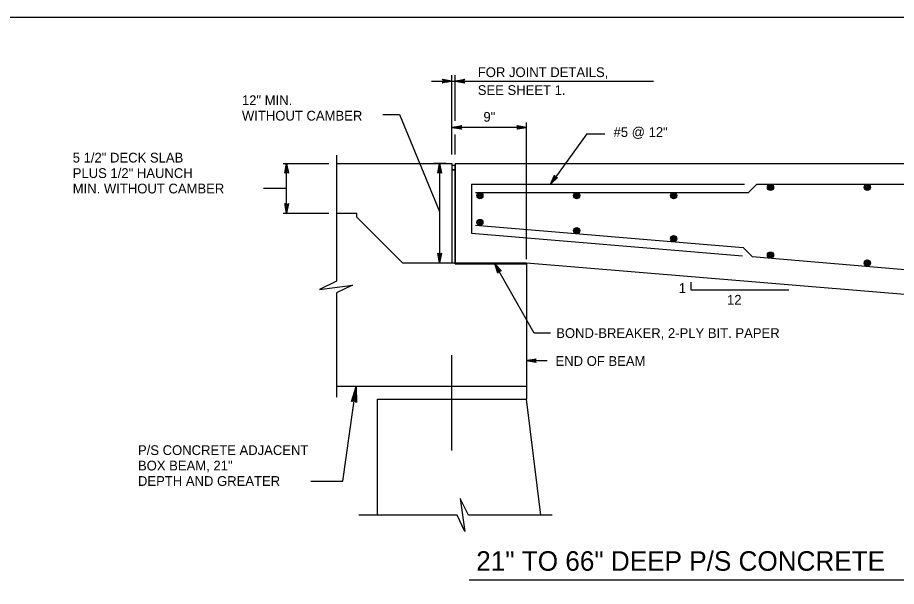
# Model space of a CAD drawing. Extents: x 638079 to 640019, y 297691 to 298879.
# Drawn here: x 638704.2 to 638974.3, y 298095.3 to 298270.2 of the extents above; entities that cross this region are included whole.
import ezdxf

# ---------------------------------------------------------------- set-up
doc = ezdxf.new("R2010")
doc.units = 0
doc.layers.add('1', color=7, linetype='Continuous')

msp = doc.modelspace()

# ---------------------------------------------------------------- linework, layer by layer
at = {"layer": '1'}
for p, q in [((638831.35, 298250.68), (638899.57, 298250.68)), ((638837.68, 298228.12), (638837.68, 298252.54)), ((638838.63, 298238.5), (638838.63, 298252.54)), ((638860.54, 298195.99), (638860.54, 298237.97)), ((638860.54, 298236.45), (638837.68, 298236.45)), ((638838.63, 298228.12), (638838.63, 298234.3)), ((638879.1, 298234.45), (638867.94, 298218.98)), ((638879.1, 298234.45), (638884.65, 298234.45)), ((638802.14, 298227.96), (638802.14, 298189.16)), ((638785.76, 298225.33), (638799.81, 298225.33)), ((638786.87, 298210.09), (638786.87, 298225.33)), ((638802.14, 298225.33), (638837.68, 298225.33)), ((638835.93, 298225.33), (638832.14, 298225.33)), ((638833.89, 298225.33), (638833.89, 298194.85)), ((638837.68, 298225.33), (638837.68, 298194.85)), ((638837.68, 298223.42), (638838.63, 298223.42)), ((638838.63, 298225.33), (639069.29, 298225.33)), ((638838.63, 298225.33), (638838.63, 298194.85)), ((638779.73, 298217.81), (638786.87, 298217.81)), ((638843.71, 298218.98), (638843.71, 298203.9)), ((638843.71, 298218.98), (638927.53, 298218.98)), ((638928.81, 298216.44), (638931.34, 298218.98)), ((638931.34, 298218.98), (639069.48, 298218.98)), ((638844.93, 298216.44), (638928.81, 298216.44)), ((638785.76, 298210.09), (638799.81, 298210.09)), ((638802.14, 298210.09), (638808.47, 298210.09)), ((638808.47, 298208.82), (638808.47, 298210.09)), ((638822.44, 298194.85), (638808.47, 298208.82)), ((638844.93, 298206.35), (638927.17, 298199.49)), ((638843.71, 298203.9), (638926.96, 298196.96)), ((638927.17, 298199.49), (638929.95, 298196.72)), ((638929.95, 298196.72), (638982.77, 298192.31)), ((638822.44, 298194.85), (638860.54, 298194.85)), ((638838.63, 298194.85), (638860.54, 298194.85)), ((638838.63, 298194.55), (638838.63, 298194.85)), ((638838.63, 298194.55), (638838.63, 298194.85)), ((638838.63, 298194.55), (638860.54, 298194.55)), ((638860.54, 298194.85), (638860.54, 298152.94)), ((638860.54, 298194.85), (638982.45, 298184.69)), ((638802.14, 298185.64), (638802.14, 298153.56)), ((638837.68, 298137.11), (638837.68, 298166.41)), ((638860.54, 298164.75), (638866.94, 298164.75)), ((638860.54, 298156.75), (638802.14, 298156.75)), ((638804.11, 298127.72), (638808.26, 298156.75)), ((638814.82, 298152.94), (638860.54, 298152.94)), ((638814.82, 298117.2), (638814.82, 298152.94)), ((638865.01, 298117.2), (638860.54, 298152.94)), ((638794.31, 298127.72), (638804.11, 298127.72)), ((638839.26, 298117.2), (638809.08, 298117.2)), ((638868.45, 298117.2), (638842.77, 298117.2)), ((638842.97, 298097.37), (639012.44, 298097.37))]:
    msp.add_line(p, q, dxfattribs=at)
for points in [[(639099.03, 297706.23), (639099.03, 298270.23), (638313.03, 298270.23), (638313.03, 297706.23), (639099.03, 297706.23), (639099.03, 297732.59), (638899.03, 297732.59), (638899.03, 297797.26), (639099.03, 297797.26), (639099.03, 297826.23), (638899.03, 297826.23), (638899.03, 297706.23), (638977.83, 297706.23), (638977.83, 297732.59), (638977.83, 297706.23), (639054.83, 297706.23), (639054.83, 297732.59), (639054.83, 297720.27), (639099.03, 297720.27)], [(638837.68, 298250.68), (638834.7, 298250.12), (638834.81, 298250.2), (638834.93, 298250.28), (638834.99, 298250.38), (638835.05, 298250.48), (638835.06, 298250.58), (638835.08, 298250.68), (638835.06, 298250.78), (638835.05, 298250.88), (638834.99, 298250.98), (638834.93, 298251.08), (638834.81, 298251.16), (638834.7, 298251.24), (638837.68, 298250.68), (638834.81, 298251.16), (638834.93, 298251.08), (638837.68, 298250.68), (638834.99, 298250.98), (638835.05, 298250.88), (638837.68, 298250.68), (638835.06, 298250.78), (638835.08, 298250.68), (638837.68, 298250.68), (638835.06, 298250.58), (638835.05, 298250.48), (638837.68, 298250.68), (638834.99, 298250.38), (638834.93, 298250.28), (638837.68, 298250.68), (638834.81, 298250.2)], [(638838.63, 298250.68), (638841.62, 298251.24), (638841.5, 298251.16), (638841.39, 298251.08), (638841.33, 298250.98), (638841.27, 298250.88), (638841.25, 298250.78), (638841.23, 298250.68), (638841.25, 298250.58), (638841.27, 298250.48), (638841.33, 298250.38), (638841.39, 298250.28), (638841.5, 298250.2), (638841.62, 298250.12), (638838.63, 298250.68), (638841.5, 298250.2), (638841.39, 298250.28), (638838.63, 298250.68), (638841.33, 298250.38), (638841.27, 298250.48), (638838.63, 298250.68), (638841.25, 298250.58), (638841.23, 298250.68), (638838.63, 298250.68), (638841.25, 298250.78), (638841.27, 298250.88), (638838.63, 298250.68), (638841.33, 298250.98), (638841.39, 298251.08), (638838.63, 298250.68), (638841.5, 298251.16)], [(638816.47, 298240.47), (638821.56, 298240.47), (638833.89, 298210.63)], [(638837.68, 298236.45), (638840.66, 298237.01), (638840.55, 298236.93), (638840.43, 298236.85), (638840.37, 298236.75), (638840.31, 298236.65), (638840.3, 298236.55), (638840.28, 298236.45), (638840.3, 298236.35), (638840.31, 298236.25), (638840.37, 298236.15), (638840.43, 298236.05), (638840.55, 298235.98), (638840.66, 298235.9), (638837.68, 298236.45), (638840.55, 298235.98), (638840.43, 298236.05), (638837.68, 298236.45), (638840.37, 298236.15), (638840.31, 298236.25), (638837.68, 298236.45), (638840.3, 298236.35), (638840.28, 298236.45), (638837.68, 298236.45), (638840.3, 298236.55), (638840.31, 298236.65), (638837.68, 298236.45), (638840.37, 298236.75), (638840.43, 298236.85), (638837.68, 298236.45), (638840.55, 298236.93)], [(638860.54, 298236.45), (638857.56, 298235.9), (638857.67, 298235.98), (638857.79, 298236.05), (638857.85, 298236.15), (638857.91, 298236.25), (638857.92, 298236.35), (638857.94, 298236.45), (638857.92, 298236.55), (638857.91, 298236.65), (638857.85, 298236.75), (638857.79, 298236.85), (638857.67, 298236.93), (638857.56, 298237.01), (638860.54, 298236.45), (638857.67, 298236.93), (638857.79, 298236.85), (638860.54, 298236.45), (638857.85, 298236.75), (638857.91, 298236.65), (638860.54, 298236.45), (638857.92, 298236.55), (638857.94, 298236.45), (638860.54, 298236.45), (638857.92, 298236.35), (638857.91, 298236.25), (638860.54, 298236.45), (638857.85, 298236.15), (638857.79, 298236.05), (638860.54, 298236.45), (638857.67, 298235.98)], [(638786.87, 298225.33), (638787.43, 298222.35), (638787.35, 298222.46), (638787.27, 298222.58), (638787.17, 298222.64), (638787.07, 298222.7), (638786.97, 298222.72), (638786.87, 298222.73), (638786.77, 298222.72), (638786.67, 298222.7), (638786.57, 298222.64), (638786.47, 298222.58), (638786.39, 298222.46), (638786.32, 298222.35), (638786.87, 298225.33), (638786.39, 298222.46), (638786.47, 298222.58), (638786.87, 298225.33), (638786.57, 298222.64), (638786.67, 298222.7), (638786.87, 298225.33), (638786.77, 298222.72), (638786.87, 298222.73), (638786.87, 298225.33), (638786.97, 298222.72), (638787.07, 298222.7), (638786.87, 298225.33), (638787.17, 298222.64), (638787.27, 298222.58), (638786.87, 298225.33), (638787.35, 298222.46)], [(638833.89, 298225.33), (638834.45, 298222.35), (638834.37, 298222.46), (638834.29, 298222.58), (638834.19, 298222.64), (638834.09, 298222.7), (638833.99, 298222.72), (638833.89, 298222.73), (638833.79, 298222.72), (638833.69, 298222.7), (638833.59, 298222.64), (638833.49, 298222.58), (638833.41, 298222.46), (638833.33, 298222.35), (638833.89, 298225.33), (638833.41, 298222.46), (638833.49, 298222.58), (638833.89, 298225.33), (638833.59, 298222.64), (638833.69, 298222.7), (638833.89, 298225.33), (638833.79, 298222.72), (638833.89, 298222.73), (638833.89, 298225.33), (638833.99, 298222.72), (638834.09, 298222.7), (638833.89, 298225.33), (638834.19, 298222.64), (638834.29, 298222.58), (638833.89, 298225.33), (638834.37, 298222.46)], [(638867.94, 298218.98), (638869.23, 298221.73), (638869.23, 298221.59), (638869.22, 298221.45), (638869.27, 298221.34), (638869.32, 298221.24), (638869.39, 298221.16), (638869.46, 298221.09), (638869.55, 298221.05), (638869.64, 298221), (638869.76, 298220.99), (638869.87, 298220.98), (638870, 298221.03), (638870.14, 298221.07), (638867.94, 298218.98), (638870, 298221.03), (638869.87, 298220.98), (638867.94, 298218.98), (638869.76, 298220.99), (638869.64, 298221), (638867.94, 298218.98), (638869.55, 298221.05), (638869.46, 298221.09), (638867.94, 298218.98), (638869.39, 298221.16), (638869.32, 298221.24), (638867.94, 298218.98), (638869.27, 298221.34), (638869.22, 298221.45), (638867.94, 298218.98), (638869.23, 298221.59)], [(638786.87, 298210.09), (638786.32, 298213.08), (638786.39, 298212.96), (638786.47, 298212.85), (638786.57, 298212.79), (638786.67, 298212.73), (638786.77, 298212.71), (638786.87, 298212.69), (638786.97, 298212.71), (638787.07, 298212.73), (638787.17, 298212.79), (638787.27, 298212.85), (638787.35, 298212.96), (638787.43, 298213.08), (638786.87, 298210.09), (638787.35, 298212.96), (638787.27, 298212.85), (638786.87, 298210.09), (638787.17, 298212.79), (638787.07, 298212.73), (638786.87, 298210.09), (638786.97, 298212.71), (638786.87, 298212.69), (638786.87, 298210.09), (638786.77, 298212.71), (638786.67, 298212.73), (638786.87, 298210.09), (638786.57, 298212.79), (638786.47, 298212.85), (638786.87, 298210.09), (638786.39, 298212.96)], [(638833.89, 298194.85), (638833.33, 298197.84), (638833.41, 298197.72), (638833.49, 298197.61), (638833.59, 298197.55), (638833.69, 298197.49), (638833.79, 298197.47), (638833.89, 298197.45), (638833.99, 298197.47), (638834.09, 298197.49), (638834.19, 298197.55), (638834.29, 298197.61), (638834.37, 298197.72), (638834.45, 298197.84), (638833.89, 298194.85), (638834.37, 298197.72), (638834.29, 298197.61), (638833.89, 298194.85), (638834.19, 298197.55), (638834.09, 298197.49), (638833.89, 298194.85), (638833.99, 298197.47), (638833.89, 298197.45), (638833.89, 298194.85), (638833.79, 298197.47), (638833.69, 298197.49), (638833.89, 298194.85), (638833.59, 298197.55), (638833.49, 298197.61), (638833.89, 298194.85), (638833.41, 298197.72)], [(638867.97, 298173.21), (638862.97, 298173.21), (638850.8, 298194.55)], [(638850.8, 298194.55), (638852.77, 298192.23), (638852.64, 298192.29), (638852.51, 298192.35), (638852.4, 298192.36), (638852.28, 298192.36), (638852.19, 298192.32), (638852.09, 298192.29), (638852.01, 298192.22), (638851.93, 298192.16), (638851.88, 298192.06), (638851.82, 298191.96), (638851.81, 298191.82), (638851.79, 298191.68), (638850.8, 298194.55), (638851.81, 298191.82), (638851.82, 298191.96), (638850.8, 298194.55), (638851.88, 298192.06), (638851.93, 298192.16), (638850.8, 298194.55), (638852.01, 298192.22), (638852.09, 298192.29), (638850.8, 298194.55), (638852.19, 298192.32), (638852.28, 298192.36), (638850.8, 298194.55), (638852.4, 298192.36), (638852.51, 298192.35), (638850.8, 298194.55), (638852.64, 298192.29)], [(638802.14, 298189.16), (638796.96, 298186.62), (638807.11, 298188), (638802.14, 298185.64)], [(638941.18, 298186.42), (638911.18, 298186.42), (638911.18, 298188.92)], [(638860.54, 298164.75), (638863.52, 298165.31), (638863.41, 298165.23), (638863.29, 298165.15), (638863.23, 298165.05), (638863.17, 298164.95), (638863.16, 298164.85), (638863.14, 298164.75), (638863.16, 298164.65), (638863.17, 298164.55), (638863.23, 298164.45), (638863.29, 298164.35), (638863.41, 298164.27), (638863.52, 298164.19), (638860.54, 298164.75), (638863.41, 298164.27), (638863.29, 298164.35), (638860.54, 298164.75), (638863.23, 298164.45), (638863.17, 298164.55), (638860.54, 298164.75), (638863.16, 298164.65), (638863.14, 298164.75), (638860.54, 298164.75), (638863.16, 298164.85), (638863.17, 298164.95), (638860.54, 298164.75), (638863.23, 298165.05), (638863.29, 298165.15), (638860.54, 298164.75), (638863.41, 298165.23)], [(638807.05, 298152.34), (638807.4, 298152.46), (638808.26, 298156.75), (638807.05, 298152.34), (638806.82, 298152.14), (638808.26, 298156.75), (638807.85, 298152.4), (638808.15, 298152.19), (638808.26, 298156.75), (638808.33, 298151.92), (638808.15, 298152.19)], [(638842.77, 298117.2), (638840.24, 298122.38), (638841.62, 298112.23), (638839.26, 298117.2)]]:
    msp.add_lwpolyline(points, dxfattribs=at)
for points in [[(638837.68, 298223.42), (638838.63, 298223.42), (638838.63, 298224.7), (638837.68, 298224.7)], [(638837.68, 298194.85), (638838.63, 298194.85), (638838.63, 298223.42), (638837.68, 298223.42)]]:
    msp.add_lwpolyline(points, close=True, dxfattribs=at)
for centre, radius in [((638935.55, 298218.03), 0.952), ((638935.55, 298218.03), 0.714), ((638935.55, 298218.03), 0.476), ((638935.55, 298218.03), 0.238), ((638965.31, 298218.03), 0.952), ((638965.31, 298218.03), 0.714), ((638965.31, 298218.03), 0.476), ((638965.31, 298218.03), 0.238), ((638846.25, 298215.49), 0.952), ((638846.25, 298215.49), 0.714), ((638846.25, 298215.49), 0.476), ((638846.25, 298215.49), 0.238), ((638876.02, 298215.49), 0.952), ((638876.02, 298215.49), 0.714), ((638876.02, 298215.49), 0.476), ((638876.02, 298215.49), 0.238), ((638905.78, 298215.49), 0.952), ((638905.78, 298215.49), 0.714), ((638905.78, 298215.49), 0.476), ((638905.78, 298215.49), 0.238), ((638846.25, 298207.23), 0.952), ((638846.25, 298207.23), 0.714), ((638846.25, 298207.23), 0.476), ((638846.25, 298207.23), 0.238), ((638876.02, 298204.72), 0.952), ((638876.02, 298204.72), 0.714), ((638876.02, 298204.72), 0.476), ((638876.02, 298204.72), 0.238), ((638905.78, 298202.22), 0.952), ((638905.78, 298202.22), 0.714), ((638905.78, 298202.22), 0.476), ((638905.78, 298202.22), 0.238), ((638935.55, 298197.19), 0.952), ((638935.55, 298197.19), 0.714), ((638935.55, 298197.19), 0.476), ((638935.55, 298197.19), 0.238), ((638965.31, 298194.75), 0.952), ((638965.31, 298194.75), 0.714), ((638965.31, 298194.75), 0.476), ((638965.31, 298194.75), 0.238)]:
    msp.add_circle(centre, radius, dxfattribs=at)

# ---------------------------------------------------------------- texts
for s, height, p in [('FOR JOINT DETAILS,', 3, (638845.6, 298251.93)), ('SEE SHEET 1.', 3, (638845.6, 298246.43)), ('12" MIN.', 3, (638773.13, 298243.31)), ('WITHOUT CAMBER', 3, (638773.13, 298238.56)), ('9"', 3, (638847.33, 298238.21)), ('#5 @ 12"', 3, (638887.33, 298233.53)), ('5 1/2" DECK SLAB', 3, (638721.13, 298225.66)), ('PLUS 1/2" HAUNCH', 3, (638721.13, 298220.91)), ('MIN. WITHOUT CAMBER', 3, (638721.13, 298216.16)), ('1', 3, (638907.38, 298185.57)), ('12', 3, (638922.2, 298181.96)), ('BOND-BREAKER, 2-PLY BIT. PAPER', 3, (638869.71, 298171.72)), ('END OF BEAM', 3, (638869.49, 298163.13)), ('P/S CONCRETE ADJACENT', 3, (638741.18, 298135.73)), ('BOX BEAM, 21"', 3, (638741.18, 298130.98)), ('DEPTH AND GREATER', 3, (638741.18, 298126.24)), ('21" TO 66" DEEP P/S CONCRETE', 6, (638845.13, 298100.15))]:
    msp.add_text(s, height=height, dxfattribs=at).set_placement(p)

doc.saveas('drawing.dxf')
